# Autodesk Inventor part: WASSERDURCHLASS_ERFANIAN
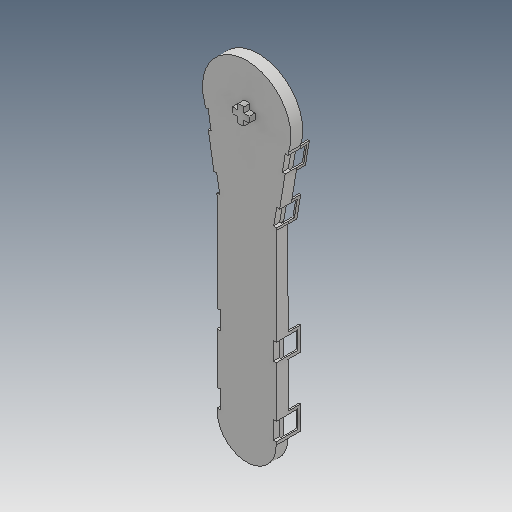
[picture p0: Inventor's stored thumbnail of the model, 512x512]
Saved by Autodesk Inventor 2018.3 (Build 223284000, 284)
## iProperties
Created: 2019-01
Part Number: WASSERDURCHLASS_ERFANIAN
Material: Generisch
Document SubType Name: Modeling
Designer: zand
Density: 1 g/cm^3
Appearance: Vorgabe
Mass: 5.54793 g
Surface Area: 77.6389 cm^2
Volume: 5.54793 cm^3
Author: zand
Revision Number: 12LAST_VERSION
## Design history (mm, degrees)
feature "Basis1"
node "Volumenkörper1"
